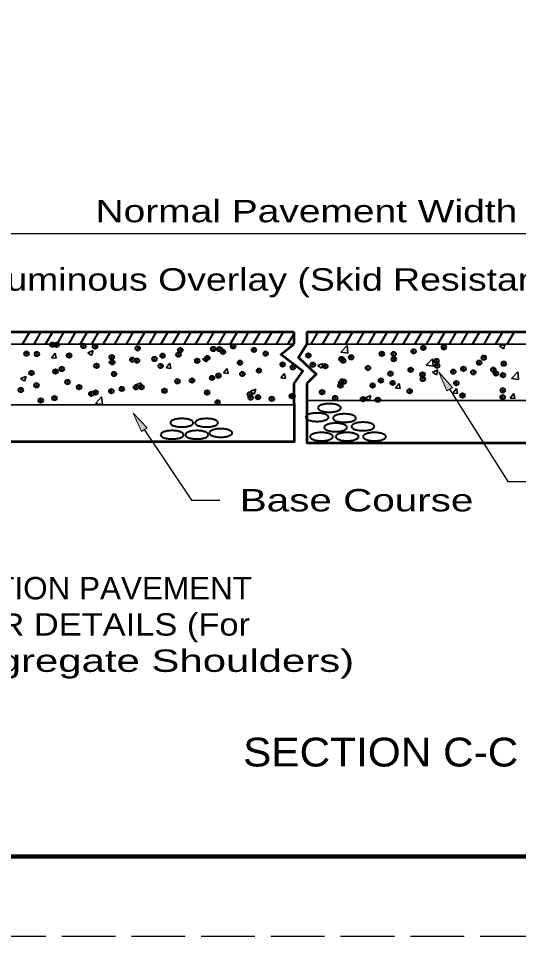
# Model space of a CAD drawing. Extents: x 36.4 to 71.7, y 0.5 to 22.5.
# Drawn here: x 53.99 to 57.12, y 0.48 to 6.22 of the extents above; entities that cross this region are included whole.
import ezdxf

# ---------------------------------------------------------------- set-up
doc = ezdxf.new("R2010")
doc.units = 0
doc.header["$LTSCALE"] = 0.056
doc.header["$PDMODE"] = 32
doc.header["$PDSIZE"] = 0.028
doc.linetypes.add('LONG_DASHED', pattern=[7.5, 6, -1.5])
doc.layers.add('1', color=7, linetype='Continuous', lineweight=40)
doc.layers.add('3', color=7, linetype='Continuous', lineweight=13)

msp = doc.modelspace()

# ---------------------------------------------------------------- hatches: boundary and pattern name
at = {"layer": '3'}
for points in [[(56.66875, 3.88933), (56.70408, 3.91158), (56.61983, 4.00617), (56.61983, 4.00617)], [(54.76017, 3.63558), (54.79475, 3.65875), (54.70792, 3.75108), (54.70792, 3.75108)]]:
    msp.add_hatch(color=256, dxfattribs=at).paths.add_polyline_path(points)

# ---------------------------------------------------------------- linework, layer by layer
at = {"layer": '1', "lineweight": 25}
msp.add_line((52.59792, 4.87367), (58.88025, 4.87367), dxfattribs=at)
at = {"layer": '1', "lineweight": 53}
for p, q in [((51.69492, 4.25908), (55.71225, 4.25908)), ((55.71225, 4.25908), (55.71225, 4.1815)), ((55.79492, 4.25908), (55.79492, 4.1815)), ((55.79492, 4.25908), (61.58058, 4.25908)), ((55.79492, 3.93467), (55.79492, 3.82925))]:
    msp.add_line(p, q, dxfattribs=at)
at = {"layer": '1'}
for p, q in [((54.01583, 4.1815), (54.06058, 4.25908)), ((54.088, 4.1815), (54.13275, 4.25908)), ((54.16017, 4.1815), (54.20492, 4.25908)), ((54.23233, 4.1815), (54.27708, 4.25908)), ((54.3045, 4.1815), (54.34925, 4.25908)), ((54.37667, 4.1815), (54.42142, 4.25908)), ((54.44883, 4.1815), (54.49358, 4.25908)), ((54.521, 4.1815), (54.56575, 4.25908)), ((54.59317, 4.1815), (54.63792, 4.25908)), ((54.66533, 4.1815), (54.71008, 4.25908)), ((54.7375, 4.1815), (54.78225, 4.25908)), ((54.80967, 4.1815), (54.85442, 4.25908)), ((54.88183, 4.1815), (54.92658, 4.25908)), ((54.954, 4.1815), (54.99883, 4.25908)), ((55.02617, 4.1815), (55.071, 4.25908)), ((55.09833, 4.1815), (55.14317, 4.25908)), ((55.1705, 4.1815), (55.21533, 4.25908)), ((55.24267, 4.1815), (55.2875, 4.25908)), ((55.31483, 4.1815), (55.35967, 4.25908)), ((55.387, 4.1815), (55.43183, 4.25908)), ((55.45917, 4.1815), (55.504, 4.25908)), ((55.53133, 4.1815), (55.57617, 4.25908)), ((55.6035, 4.1815), (55.64833, 4.25908)), ((55.82, 4.1815), (55.86483, 4.25908)), ((55.89217, 4.1815), (55.937, 4.25908)), ((55.96433, 4.1815), (56.00917, 4.25908)), ((56.0365, 4.1815), (56.08133, 4.25908)), ((56.10875, 4.1815), (56.1535, 4.25908)), ((56.18092, 4.1815), (56.22567, 4.25908)), ((56.25308, 4.1815), (56.29783, 4.25908)), ((56.32525, 4.1815), (56.37, 4.25908)), ((56.39742, 4.1815), (56.44217, 4.25908)), ((56.46958, 4.1815), (56.51433, 4.25908)), ((56.54175, 4.1815), (56.5865, 4.25908)), ((56.61392, 4.1815), (56.65867, 4.25908)), ((56.68608, 4.1815), (56.73083, 4.25908)), ((56.75825, 4.1815), (56.803, 4.25908)), ((56.83042, 4.1815), (56.87517, 4.25908)), ((56.90258, 4.1815), (56.94733, 4.25908)), ((56.97475, 4.1815), (57.0195, 4.25908)), ((57.04692, 4.1815), (57.09167, 4.25908)), ((55.67567, 4.1815), (55.71225, 4.24483))]:
    msp.add_line(p, q, dxfattribs=at)
at = {"layer": '1', "lineweight": 35}
for p, q in [((54.42342, 4.12767), (54.45842, 4.14108)), ((54.44825, 4.11083), (54.45842, 4.14108)), ((55.79492, 4.1815), (59.02792, 4.1815)), ((56.00633, 4.13258), (56.04533, 4.17325)), ((56.05083, 4.12575), (56.04533, 4.17317)), ((56.99925, 4.16875), (57.0325, 4.1815)), ((56.99925, 4.16875), (57.02408, 4.152)), ((57.02408, 4.152), (57.034, 4.1815)), ((54.19617, 4.09575), (54.22033, 4.1245)), ((54.19617, 4.09575), (54.22608, 4.09317)), ((54.22608, 4.09317), (54.22033, 4.1245)), ((54.42342, 4.12767), (54.44825, 4.11083)), ((54.55483, 4.06442), (54.57892, 4.09317)), ((54.58475, 4.06175), (54.57892, 4.09308)), ((55.142, 4.08758), (55.177, 4.101)), ((55.142, 4.08758), (55.16683, 4.07083)), ((55.16683, 4.07083), (55.177, 4.101)), ((56.00633, 4.13258), (56.05083, 4.12575)), ((56.54, 4.04983), (56.57892, 4.09042)), ((56.58442, 4.04292), (56.57892, 4.09042)), ((54.55483, 4.06442), (54.58475, 4.06175)), ((54.9135, 4.033), (54.93758, 4.06175)), ((54.9135, 4.033), (54.94333, 4.03042)), ((54.94333, 4.03042), (54.93758, 4.06175)), ((55.27208, 4.00167), (55.29617, 4.03042)), ((55.302, 3.999), (55.29617, 4.03033)), ((55.86058, 4.0475), (55.89558, 4.061)), ((55.86058, 4.0475), (55.88542, 4.03075)), ((55.88542, 4.03075), (55.89558, 4.061)), ((56.54, 4.04983), (56.58442, 4.043)), ((56.57908, 4.0075), (56.61408, 4.02092)), ((56.604, 3.99067), (56.61408, 4.02092)), ((54.00333, 3.96633), (54.03833, 3.97983)), ((54.00333, 3.96633), (54.02817, 3.94958)), ((54.02817, 3.94958), (54.03833, 3.97975)), ((55.27208, 4.00167), (55.302, 3.999)), ((55.63075, 3.97025), (55.65483, 3.999)), ((55.63075, 3.97025), (55.66058, 3.96767)), ((55.66058, 3.96767), (55.65483, 3.999)), ((55.98933, 3.93892), (56.01342, 3.96767)), ((56.01925, 3.93625), (56.01342, 3.96758)), ((56.57908, 4.0075), (56.604, 3.99075)), ((57.07358, 3.96708), (57.11258, 4.00767)), ((57.07358, 3.96708), (57.11808, 3.96017)), ((57.11808, 3.96017), (57.11258, 4.00767)), ((54.72183, 3.92633), (54.75692, 3.93975)), ((54.72183, 3.92633), (54.74675, 3.90958)), ((54.74675, 3.9095), (54.75692, 3.93975)), ((55.98933, 3.93892), (56.01925, 3.93625)), ((56.348, 3.9075), (56.37208, 3.93625)), ((56.348, 3.9075), (56.37783, 3.90492)), ((56.37783, 3.90492), (56.37208, 3.93625)), ((56.70658, 3.87617), (56.73075, 3.90483)), ((56.7365, 3.8735), (56.73075, 3.90483)), ((54.47175, 3.81108), (54.51075, 3.85167)), ((54.51625, 3.80417), (54.51075, 3.85167)), ((55.44042, 3.88625), (55.47542, 3.89975)), ((55.44042, 3.88625), (55.46533, 3.8695)), ((55.46533, 3.8695), (55.47542, 3.89967)), ((56.159, 3.84625), (56.194, 3.85967)), ((56.18383, 3.82942), (56.194, 3.85967)), ((56.70658, 3.87617), (56.7365, 3.8735)), ((57.06525, 3.84475), (57.08933, 3.8735)), ((57.09517, 3.84217), (57.08933, 3.8735)), ((54.47175, 3.81108), (54.51625, 3.80417)), ((59.02792, 3.82925), (55.79492, 3.82925)), ((56.159, 3.84625), (56.18383, 3.82942)), ((57.06525, 3.84475), (57.09517, 3.84217))]:
    msp.add_line(p, q, dxfattribs=at)
at = {"layer": '1', "linetype": 'LONG_DASHED', "lineweight": 25}
msp.add_line((71.60142, 0.47742), (36.40142, 0.47742), dxfattribs=at)
at = {"layer": '1', "lineweight": 158}
msp.add_lwpolyline([(71.51808, 21.97742), (71.51808, 0.97742), (39.01808, 0.97742)], dxfattribs=at)
at = {"layer": '1', "lineweight": 35}
for points in [[(52.45633, 4.25908), (52.45633, 4.1815), (55.71225, 4.1815)], [(52.45633, 4.1815), (52.45633, 3.80325), (55.71417, 3.80325)]]:
    msp.add_lwpolyline(points, dxfattribs=at)
at = {"layer": '1', "lineweight": 53}
for points in [[(55.71417, 3.80325), (55.71417, 3.93658), (55.76942, 4.01192), (55.63125, 4.11633), (55.71225, 4.1815)], [(55.79492, 4.1815), (55.7415, 4.09892), (55.852, 3.99458), (55.79492, 3.93467)], [(55.71417, 3.809), (55.71417, 3.57133), (51.89333, 3.57133)], [(55.79492, 3.82925), (55.79492, 3.56558), (61.47658, 3.56558)]]:
    msp.add_lwpolyline(points, dxfattribs=at)
at = {"layer": '1'}
for centre, radius, start, end in [((55.87425, 3.78292), 0.01098, 131.1756, 179.93648), ((55.90292, 3.75017), 0.05453, 109.95668, 131.23889), ((55.92217, 3.69683), 0.11118, 98.4919, 109.89511), ((55.93492, 3.61125), 0.19777, 89.93573, 98.48922), ((55.93533, 3.61183), 0.19721, 81.49885, 90.05234), ((55.94808, 3.69683), 0.11118, 70.10489, 81.5081), ((55.96733, 3.75017), 0.05453, 48.76111, 70.04332), ((55.996, 3.78292), 0.01098, 0.06351, 48.82439), ((55.79683, 3.72492), 0.01089, 130.95574, 179.71662), ((55.82558, 3.69242), 0.05433, 110.0778, 131.36001), ((55.84483, 3.63842), 0.11159, 98.43909, 109.84231), ((55.85817, 3.55383), 0.19725, 90.10951, 98.663), ((55.85742, 3.55325), 0.19781, 81.34937, 89.90286), ((55.87417, 3.783), 0.01089, 180.28337, 229.04425), ((55.90292, 3.81575), 0.05453, 228.76111, 250.04332), ((55.92217, 3.86908), 0.11118, 250.10489, 261.5081), ((55.87075, 3.63883), 0.11118, 70.10489, 81.5081), ((55.9355, 3.95467), 0.19781, 261.34937, 269.90286), ((55.89, 3.69217), 0.05453, 48.76111, 70.04332), ((55.91875, 3.725), 0.01084, 359.79866, 48.55954), ((55.93475, 3.95408), 0.19725, 270.10951, 278.663), ((55.99683, 3.68642), 0.05453, 109.95668, 131.23889), ((55.94808, 3.86908), 0.11118, 278.4919, 289.89511), ((56.01617, 3.63267), 0.11159, 98.43909, 109.84231), ((55.96733, 3.81575), 0.05453, 289.95668, 311.23889), ((56.02892, 3.54808), 0.19721, 89.94766, 98.50115), ((55.99608, 3.783), 0.01089, 310.95574, 359.71662), ((56.02925, 3.54808), 0.19721, 81.49885, 90.05234), ((56.042, 3.63267), 0.11159, 70.15769, 81.5609), ((56.06133, 3.68642), 0.05453, 48.76111, 70.04332), ((54.95125, 3.69025), 0.01094, 131.65707, 180.41795), ((54.95117, 3.69017), 0.01084, 179.79866, 228.55954), ((54.97992, 3.65742), 0.05453, 109.95668, 131.23889), ((54.97992, 3.723), 0.05453, 228.76111, 250.04332), ((54.99925, 3.60367), 0.11159, 98.43909, 109.84231), ((55.012, 3.51908), 0.19721, 89.94766, 98.50115), ((55.01242, 3.5185), 0.19777, 81.51077, 90.06427), ((55.02517, 3.60408), 0.11118, 70.10489, 81.5081), ((55.04442, 3.65742), 0.05453, 48.76111, 70.04332), ((55.04442, 3.723), 0.05453, 289.95668, 311.23889), ((55.07308, 3.69025), 0.01094, 359.58205, 48.34293), ((55.07317, 3.69017), 0.01084, 311.44045, 0.20133), ((55.106, 3.69025), 0.01094, 131.65707, 180.41795), ((55.10592, 3.69017), 0.01084, 179.79866, 228.55954), ((55.13467, 3.65742), 0.05453, 109.95668, 131.23889), ((55.13467, 3.723), 0.05453, 228.76111, 250.04332), ((55.154, 3.60367), 0.11159, 98.43909, 109.84231), ((55.16675, 3.51908), 0.19721, 89.94766, 98.50115), ((55.16708, 3.51908), 0.19721, 81.49885, 90.05234), ((55.17983, 3.60367), 0.11159, 70.15769, 81.5609), ((55.19917, 3.65742), 0.05453, 48.76111, 70.04332), ((55.19917, 3.723), 0.05453, 289.95668, 311.23889), ((55.22783, 3.69025), 0.01094, 359.58205, 48.34293), ((55.22792, 3.69017), 0.01084, 311.44045, 0.20133), ((55.79692, 3.725), 0.01098, 180.06351, 228.82439), ((55.82558, 3.7575), 0.05433, 228.63999, 249.9222), ((55.84483, 3.8115), 0.11159, 250.15769, 261.5609), ((55.85758, 3.89608), 0.19721, 261.49885, 270.05234), ((55.858, 3.89667), 0.19777, 269.93573, 278.48922), ((55.87075, 3.81108), 0.11118, 278.4919, 289.89511), ((55.94158, 3.62842), 0.05453, 109.95668, 131.23889), ((55.89, 3.75775), 0.05453, 289.95668, 311.23889), ((55.96083, 3.57508), 0.11118, 98.4919, 109.89511), ((55.91867, 3.72492), 0.01094, 311.65707, 0.41795), ((55.97417, 3.4895), 0.19781, 90.09713, 98.65062), ((55.96817, 3.71925), 0.01094, 131.65707, 180.41795), ((55.96808, 3.71917), 0.01084, 179.79866, 228.55954), ((55.99683, 3.752), 0.05453, 228.76111, 250.04332), ((55.97342, 3.49008), 0.19725, 81.33699, 89.89049), ((56.01658, 3.80567), 0.11169, 249.94906, 261.35227), ((56.02892, 3.89025), 0.19721, 261.49885, 270.05234), ((55.98675, 3.57508), 0.11118, 70.10489, 81.5081), ((56.006, 3.62842), 0.05453, 48.76111, 70.04332), ((56.02925, 3.89025), 0.19721, 269.94766, 278.50115), ((56.04158, 3.80567), 0.11169, 278.64772, 290.05094), ((56.08417, 3.667), 0.01084, 131.44045, 180.20133), ((56.11292, 3.63417), 0.05453, 109.95668, 131.23889), ((56.06133, 3.752), 0.05453, 289.95668, 311.23889), ((56.13258, 3.58092), 0.11128, 98.70124, 110.10445), ((56.09008, 3.71917), 0.01084, 311.44045, 0.20133), ((56.09, 3.71925), 0.01094, 359.58205, 48.34293), ((56.14492, 3.49533), 0.19777, 89.93573, 98.48922), ((56.14533, 3.49592), 0.19721, 81.49885, 90.05234), ((56.15767, 3.58092), 0.11128, 69.89554, 81.29876), ((56.17733, 3.63417), 0.05453, 48.76111, 70.04332), ((56.20608, 3.66692), 0.01089, 0.28337, 49.04425), ((54.89042, 3.61475), 0.01089, 130.95574, 179.71662), ((54.91917, 3.582), 0.05453, 109.95668, 131.23889), ((54.93883, 3.52875), 0.11128, 98.70124, 110.10445), ((54.95117, 3.44317), 0.19777, 89.93573, 98.48922), ((54.95158, 3.44375), 0.19721, 81.49885, 90.05234), ((54.99925, 3.77675), 0.11159, 250.15769, 261.5609), ((54.96392, 3.52875), 0.11128, 69.89554, 81.29876), ((55.01258, 3.86133), 0.19725, 261.33699, 269.89049), ((54.98358, 3.582), 0.05453, 48.76111, 70.04332), ((55.01183, 3.86192), 0.19781, 270.09713, 278.65062), ((55.01233, 3.61475), 0.01089, 0.28337, 49.04425), ((55.04517, 3.61475), 0.01089, 130.95574, 179.71662), ((55.07392, 3.582), 0.05453, 109.95668, 131.23889), ((55.02517, 3.77633), 0.11118, 278.4919, 289.89511), ((55.09358, 3.52875), 0.11128, 98.70124, 110.10445), ((55.10592, 3.44375), 0.19721, 89.94766, 98.50115), ((55.10633, 3.44317), 0.19777, 81.51077, 90.06427), ((55.154, 3.77675), 0.11159, 250.15769, 261.5609), ((55.11867, 3.52875), 0.11128, 69.89554, 81.29876), ((55.16733, 3.86133), 0.19725, 261.33699, 269.89049), ((55.13833, 3.582), 0.05453, 48.76111, 70.04332), ((55.1665, 3.86133), 0.19725, 270.10951, 278.663), ((55.16708, 3.61475), 0.01089, 0.28337, 49.04425), ((55.19442, 3.62633), 0.01089, 130.95574, 179.71662), ((55.19442, 3.6265), 0.01089, 180.28337, 229.04425), ((55.22317, 3.59383), 0.05433, 110.0778, 131.36001), ((55.22317, 3.659), 0.05433, 228.63999, 249.9222), ((55.17983, 3.77675), 0.11159, 278.43909, 289.84231), ((55.24283, 3.53992), 0.11169, 98.64772, 110.05094), ((55.25517, 3.45533), 0.19721, 89.94766, 98.50115), ((55.25558, 3.45475), 0.19777, 81.51077, 90.06427), ((55.26792, 3.54033), 0.11128, 69.89554, 81.29876), ((55.28758, 3.59358), 0.05453, 48.76111, 70.04332), ((55.28758, 3.65925), 0.05453, 289.95668, 311.23889), ((55.31633, 3.62642), 0.01084, 359.79866, 48.55954), ((55.31633, 3.62642), 0.01084, 311.44045, 0.20133), ((55.85317, 3.57042), 0.05453, 109.95668, 131.23889), ((55.87242, 3.51708), 0.11118, 98.4919, 109.89511), ((55.88575, 3.4315), 0.19781, 90.09713, 98.65062), ((55.885, 3.43208), 0.19725, 81.33699, 89.89049), ((55.91292, 3.66125), 0.01094, 131.65707, 180.41795), ((55.91283, 3.66117), 0.01084, 179.79866, 228.55954), ((55.94158, 3.694), 0.05453, 228.76111, 250.04332), ((55.89833, 3.51708), 0.11118, 70.10489, 81.5081), ((55.96083, 3.74733), 0.11118, 250.10489, 261.5081), ((55.91758, 3.57042), 0.05453, 48.76111, 70.04332), ((55.97417, 3.83292), 0.19781, 261.34937, 269.90286), ((55.97342, 3.83233), 0.19725, 270.10951, 278.663), ((56.01342, 3.57042), 0.05453, 109.95668, 131.23889), ((56.03267, 3.51708), 0.11118, 98.4919, 109.89511), ((55.98675, 3.74733), 0.11118, 278.4919, 289.89511), ((56.046, 3.4315), 0.19781, 90.09713, 98.65062), ((56.006, 3.694), 0.05453, 289.95668, 311.23889), ((56.03475, 3.66125), 0.01089, 310.95574, 359.71662), ((56.03467, 3.66117), 0.01098, 0.06351, 48.82439), ((56.04525, 3.43208), 0.19725, 81.33699, 89.89049), ((56.08417, 3.667), 0.01084, 179.79866, 228.55954), ((56.05858, 3.51667), 0.11159, 70.15769, 81.5609), ((56.11292, 3.69983), 0.05453, 228.76111, 250.04332), ((56.13258, 3.75308), 0.11128, 249.89554, 261.29876), ((56.07792, 3.57042), 0.05453, 48.76111, 70.04332), ((56.14492, 3.83867), 0.19777, 261.51077, 270.06427), ((56.14533, 3.83808), 0.19721, 269.94766, 278.50115), ((56.18475, 3.57042), 0.05453, 109.95668, 131.23889), ((56.204, 3.51708), 0.11118, 98.4919, 109.89511), ((56.15767, 3.75308), 0.11128, 278.70124, 290.10445), ((56.21733, 3.4315), 0.19781, 90.09713, 98.65062), ((56.17733, 3.69983), 0.05453, 289.95668, 311.23889), ((56.20608, 3.66708), 0.01089, 310.95574, 359.71662), ((56.21658, 3.43208), 0.19725, 81.33699, 89.89049), ((56.22992, 3.51667), 0.11159, 70.15769, 81.5609), ((56.24917, 3.57067), 0.05433, 48.63999, 69.9222), ((54.8905, 3.61483), 0.01098, 180.06351, 228.82439), ((54.919, 3.64767), 0.05441, 228.96563, 250.24784), ((54.93883, 3.70092), 0.11128, 249.89554, 261.29876), ((54.95117, 3.7865), 0.19777, 261.51077, 270.06427), ((54.95158, 3.78592), 0.19721, 269.94766, 278.50115), ((54.96392, 3.70092), 0.11128, 278.70124, 290.10445), ((54.98375, 3.64767), 0.05441, 289.75216, 311.03436), ((55.01225, 3.61483), 0.01098, 311.1756, 359.93648), ((55.04525, 3.61483), 0.01098, 180.06351, 228.82439), ((55.07375, 3.64767), 0.05441, 228.96563, 250.24784), ((55.09358, 3.70092), 0.11128, 249.89554, 261.29876), ((55.10592, 3.78592), 0.19721, 261.49885, 270.05234), ((55.10633, 3.7865), 0.19777, 269.93573, 278.48922), ((55.11867, 3.70092), 0.11128, 278.70124, 290.10445), ((55.1385, 3.64767), 0.05441, 289.75216, 311.03436), ((55.167, 3.61483), 0.01098, 311.1756, 359.93648), ((55.24283, 3.71292), 0.11169, 249.94906, 261.35227), ((55.25517, 3.7975), 0.19721, 261.49885, 270.05234), ((55.25558, 3.79808), 0.19777, 269.93573, 278.48922), ((55.26792, 3.7125), 0.11128, 278.70124, 290.10445), ((55.8245, 3.60317), 0.01094, 179.58205, 228.34293), ((55.82442, 3.60325), 0.01084, 131.44045, 180.20133), ((55.85317, 3.636), 0.05453, 228.76111, 250.04332), ((55.87242, 3.68933), 0.11118, 250.10489, 261.5081), ((55.88517, 3.77492), 0.19777, 261.51077, 270.06427), ((55.88558, 3.77433), 0.19721, 269.94766, 278.50115), ((55.89833, 3.68933), 0.11118, 278.4919, 289.89511), ((55.91758, 3.636), 0.05453, 289.95668, 311.23889), ((55.94633, 3.60317), 0.01089, 0.28337, 49.04425), ((55.94625, 3.60325), 0.01098, 311.1756, 359.93648), ((55.98475, 3.60317), 0.01094, 179.58205, 228.34293), ((55.98467, 3.60325), 0.01084, 131.44045, 180.20133), ((56.01342, 3.636), 0.05453, 228.76111, 250.04332), ((56.03267, 3.68933), 0.11118, 250.10489, 261.5081), ((56.04542, 3.77492), 0.19777, 261.51077, 270.06427), ((56.04583, 3.77433), 0.19721, 269.94766, 278.50115), ((56.05858, 3.68975), 0.11159, 278.43909, 289.84231), ((56.07792, 3.636), 0.05453, 289.95668, 311.23889), ((56.10667, 3.60325), 0.01084, 359.79866, 48.55954), ((56.10658, 3.60317), 0.01094, 311.65707, 0.41795), ((56.15608, 3.60317), 0.01094, 179.58205, 228.34293), ((56.156, 3.60325), 0.01084, 131.44045, 180.20133), ((56.18475, 3.636), 0.05453, 228.76111, 250.04332), ((56.204, 3.68933), 0.11118, 250.10489, 261.5081), ((56.21675, 3.77492), 0.19777, 261.51077, 270.06427), ((56.21717, 3.77433), 0.19721, 269.94766, 278.50115), ((56.22992, 3.68975), 0.11159, 278.43909, 289.84231), ((56.24917, 3.63575), 0.05433, 290.0778, 311.36001), ((56.27792, 3.60317), 0.01089, 0.28337, 49.04425), ((56.27783, 3.60325), 0.01098, 311.1756, 359.93648)]:
    msp.add_arc(centre, radius, start, end, dxfattribs=at)
for p in [(54.20242, 4.17833), (54.22825, 4.17733), (54.04092, 4.1225), (54.10583, 4.12033), (54.39742, 4.17033), (54.46933, 4.16708), (54.73625, 4.15583), (55.00317, 4.1445), (55.20767, 4.15125), (55.24792, 4.15083), (55.27, 4.13325), (55.33283, 4.16775), (55.46308, 4.14558), (55.53692, 4.122), (56.26333, 4.12108), (56.33675, 4.12), (56.46192, 4.1365), (56.523, 4.15858), (56.65125, 4.16142), (54.30783, 4.11117), (54.57475, 4.09992), (54.57733, 4.06825), (54.7025, 4.08475), (54.7315, 4.07808), (54.84167, 4.08867), (54.89183, 4.10967), (54.99117, 4.11558), (55.10858, 4.07733), (55.1715, 4.0955), (55.3755, 4.06608), (55.80383, 4.11067), (56.01075, 4.08908), (56.021, 4.07842), (56.07075, 4.09942), (56.33767, 4.08817), (56.60458, 4.07683), (56.8715, 4.06558), (56.90042, 4.0975), (54.22217, 4.01092), (54.26158, 4.02667), (54.47892, 4.04608), (54.87992, 4.04542), (55.49433, 4.01633), (55.64233, 4.05483), (55.70642, 4.037), (55.83158, 4.0535), (55.90925, 4.0435), (56.17617, 4.03225), (56.44308, 4.021), (56.60883, 4.04742), (56.71, 4.00967), (56.77367, 4.02733), (56.8355, 4.00575), (56.96067, 4.02225), (57.02625, 4.05933), (54.07217, 4.00175), (54.58833, 3.99542), (54.98508, 3.94917), (55.07608, 3.954), (55.20125, 3.9705), (55.24183, 3.98433), (55.39067, 3.99542), (56.25725, 3.95458), (56.31725, 3.99733), (56.51692, 3.99208), (56.51975, 3.96417), (56.97692, 3.99842), (57.02025, 3.98767), (54.00517, 3.89525), (54.10292, 3.92417), (54.29675, 3.94533), (54.36983, 3.91292), (54.63675, 3.90167), (54.72542, 3.91167), (54.76033, 3.91242), (54.90367, 3.89033), (56.00467, 3.92258), (56.02567, 3.94733), (56.20517, 3.92275), (56.33033, 3.93925), (56.72867, 3.93767), (57.02017, 3.89292), (54.21608, 3.84442), (54.44583, 3.871), (54.47283, 3.87967), (54.571, 3.8875), (55.17058, 3.87908), (55.4375, 3.86783), (55.4425, 3.84725), (55.48825, 3.84992), (55.57492, 3.83983), (55.70008, 3.85625), (55.70442, 3.85658), (55.88942, 3.88125), (55.97133, 3.84525), (56.1455, 3.8375), (56.23817, 3.834), (56.43708, 3.88758), (56.76758, 3.86083), (57.0185, 3.85), (54.13, 3.8295), (55.23575, 3.81792)]:
    msp.add_point(p, dxfattribs=at)
at = {"layer": '3'}
for points in [[(56.66875, 3.88933), (56.70408, 3.91158), (56.61983, 4.00617), (56.61983, 4.00617)], [(54.76017, 3.63558), (54.79475, 3.65875), (54.70792, 3.75108), (54.70792, 3.75108)]]:
    msp.add_lwpolyline(points, close=True, dxfattribs=at)
at = {"layer": '3', "lineweight": 25}
for points in [[(56.68642, 3.90042), (57.05092, 3.322), (57.31617, 3.322)], [(54.7775, 3.64717), (55.07267, 3.206), (55.2495, 3.206)]]:
    msp.add_lwpolyline(points, dxfattribs=at)

# ---------------------------------------------------------------- texts
at = {"layer": '1', "width": 1.3}
msp.add_text('Normal Pavement Width', height=0.14, dxfattribs=at).set_placement((54.47242, 4.94367))
at = {"layer": '3'}
for s, height, width, p in [('2" Bituminous Overlay (Skid Resistant Mix)', 0.14, 1.25, (53.36308, 4.51608)), ('Base Course', 0.14, 1.35, (55.3745, 3.136)), ('BRIDGE TRANSITION PAVEMENT', 0.14, 1.05, (52.31617, 2.586)), ('AND SHOULDER DETAILS (For', 0.14, 1.15, (52.31617, 2.35933)), ('Untreated Aggregate Shoulders)', 0.14, 1.4, (52.31617, 2.13267)), ('SECTION C-C', 0.18, 1.1, (55.39542, 1.54117))]:
    msp.add_text(s, height=height, dxfattribs=dict(at, width=width)).set_placement(p)

doc.saveas('drawing.dxf')
